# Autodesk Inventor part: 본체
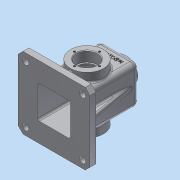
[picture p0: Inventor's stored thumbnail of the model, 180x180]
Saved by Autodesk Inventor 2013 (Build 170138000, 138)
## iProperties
Created: 2018-10
Part Number: 본체
Material: 알루미늄 6061
Document SubType Name: Modeling
Designer: Administrator
Density: 2.71 g/cm^3
Mass: 796.912 g
Surface Area: 900.061 cm^2
Volume: 294.063 cm^3
Author: Administrator
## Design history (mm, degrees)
sketch "스케치1"
  geometry: L1 (-55, 32.5)-(55, 32.5); L2 (55, 32.5)-(55, -32.5); L3 (55, -32.5)-(-55, -32.5); L4 (-55, -32.5)-(-55, 32.5); L5 (-55, 32.5)-(55, -32.5); L6 (55, 32.5)-(-55, -32.5); 1 further point
  constraints: 12 end point, 2 midpoint, 2 parallel, 1 horizontal, 1 perpendicular
  dimensions: "d0" = 110 distance of L2.end L3.end; "d1" = 65 distance of L1.end L2.end
extrude "돌출1" new body sketch "스케치1" stored distance "d2" = 65; taper "d3" = 0 deg
fillet "모깎기1" dims "d4" = 8
fillet "모깎기2" dims "d5" = 8
feature "쉘1" dims "d6" = 5
sketch "스케치2"
  geometry: L1 (57, -8)-(57, -57) reference; L2 (0, 0)-(49, 0) reference; L3 (-8, -57)-(-8, -8) reference; L4 (49, -65)-(0, -65) reference; L5 (-35.5, -92.5)-(84.5, -92.5); L6 (84.5, -92.5)-(84.5, 27.5); L7 (84.5, 27.5)-(-35.5, 27.5); L8 (-35.5, 27.5)-(-35.5, -92.5); L9 (-35.5, -92.5)-(84.5, 27.5); L10 (84.5, -92.5)-(-35.5, 27.5); A1 r 8 centre (49, -57) between (49, -65) and (57, -57) reference; A2 r 8 centre (49, -8) between (57, -8) and (49, 0) reference; A3 r 8 centre (0, -8) between (0, 0) and (-8, -8) reference; A4 r 8 centre (0, -57) between (-8, -57) and (0, -65) reference; 1 further point
  constraints: 12 end point, 2 midpoint, 2 parallel, 1 horizontal, 1 perpendicular
  dimensions: "d7" = 120 distance of L7.end L6.end; "d8" = 120 distance of L6.end L5.end
extrude "돌출2" join sketch "스케치2" distance "d9" = 10; taper "d10" = 0 deg
chamfer "모따기1" distance "d11" = 8; stored, may be unused: second distance "d12" = 2, angle "d13" = 45 deg
sketch "스케치3"
  geometry: L1 (48, -45)-(35.218, 27.493); L2 (-24.5, 55)-(24.5, 55) reference; L3 (32.5, 47)-(32.5, -45) reference; L4 (32.5, -45)-(60, -45) reference; L5 (60, -45)-(60, -55) reference; L6 (60, -55)-(27.5, -55) reference; L7 (27.5, -55)-(27.5, 47) reference; L8 (24.5, 50)-(-24.5, 50) reference; L9 (-27.5, 47)-(-27.5, -55) reference; L10 (-27.5, -55)-(-60, -55) reference; L11 (-60, -55)-(-60, -45) reference; L12 (-60, -45)-(-32.5, -45) reference; L13 (-32.5, -45)-(-32.5, 47) reference; A1 r 8 centre (-24.5, 47) between (-24.5, 55) and (-32.5, 47) reference; A2 r 8 centre (24.5, 47) between (32.5, 47) and (24.5, 55) reference; A3 r 3 centre (24.5, 47) between (27.5, 47) and (24.5, 50) reference; A4 r 3 centre (-24.5, 47) between (-24.5, 50) and (-27.5, 47) reference; 1 further point
  constraints: 2 end point, 1 point on line
  dimensions: "d14" = 12 distance from line of L5 L1.start; "d15" = 10 deg angle of L5 L1
feature "리브1" sketch "스케치3" dims "d16" = 1, "d17" = 10, "d18" = 0, "d19" = 0, "d20" = 1, "d21" = 1
fillet "모깎기3" dims "d22" = 3
fillet "모깎기4" dims "d23" = 3
node "작업 평면1"
sketch "스케치4"
  geometry: C1 r 27.5 at (24.5, -47); 1 further point
  constraints: 1 centre point, 1 coincident
  dimensions: "d26" = 55 diameter of C1
extrude "돌출3" join sketch "스케치4" stored distance "d27" = 10; taper "d28" = 0 deg
hole "구멍1" diameter "d31" = 30; stored, may be unused: countersink angle "d35" = 90 deg, drill point angle "d37" = 118 deg; dims "d29" = 10, "d30" = 10, "d32" = 6, "d33" = 35, "d34" = 17, "d36" = 20
fillet "모깎기6" dims "d38" = 0.3
chamfer "모따기2" distance "d39" = 1; stored, may be unused: second distance "d40" = 2, angle "d41" = 45 deg
sketch "스케치5"
  geometry: L1 (0, 0)-(0, 21); C1 r 18.5 at (0, 0) reference
  constraints: 2 end point, 1 vertical
  dimensions: "d42" = 21 distance of L1.start L1.end
hole "구멍2" sketch "스케치5" at (0, 21) diameter "d43" = 3.459; stored, may be unused: countersink angle "d47" = 90 deg, drill point angle "d49" = 118 deg; dims "d44" = 8, "d45" = 35, "d46" = 17, "d48" = 10
sketch "스케치6"
  geometry: L1 (-55, 27.5)-(-55, 60) reference; L2 (-55, 60)-(-45, 60) reference; L3 (-45, 60)-(-45, 32.5) reference; L4 (-45, 32.5)-(-27.5, 32.5) reference; L5 (-27.5, 32.5)-(-27.5, 47.5) reference; L6 (-27.5, 47.5)-(-22.73, 47.5) reference; L7 (-22.73, 47.5)-(-22.73, 37.5) reference; L8 (-22.73, 37.5)-(-21, 36.461) reference; L9 (-21, 36.461)-(-19.271, 37.5) reference; L10 (-19.271, 37.5)-(-19.271, 47.5) reference; L11 (-19.271, 47.5)-(-18.5, 47.5) reference; L12 (-18.5, 47.5)-(-17.5, 46.5) reference; L13 (-17.5, 46.5)-(-17.5, 30.8) reference; L14 (-17.2, 30.5)-(-15, 30.5) reference; L15 (-15, 30.5)-(-15, 27.5) reference; L16 (-15, 27.5)-(-55, 27.5) reference; L17 (50, -24.5)-(50, 24.5) reference; L18 (47, 27.5)-(15, 27.5) reference; L19 (15, 27.5)-(15, 30.5) reference; L20 (15, 30.5)-(17.2, 30.5) reference; L21 (17.5, 30.8)-(17.5, 46.5) reference; L22 (17.5, 46.5)-(18.5, 47.5) reference; L23 (18.5, 47.5)-(19.271, 47.5) reference; L24 (19.271, 47.5)-(19.271, 37.5) reference; L25 (19.271, 37.5)-(21, 36.461) reference; L26 (21, 36.461)-(22.73, 37.5) reference; L27 (22.73, 37.5)-(22.73, 47.5) reference; L28 (22.73, 47.5)-(27.5, 47.5) reference; L29 (27.5, 47.5)-(27.5, 32.5) reference; L30 (27.5, 32.5)-(47, 32.5) reference; L31 (55, 24.5)-(55, -24.5) reference; L32 (47, -32.5)-(-45, -32.5) reference; L33 (-45, -32.5)-(-45, -60) reference; L34 (-45, -60)-(-55, -60) reference; L35 (-55, -60)-(-55, -27.5) reference; L36 (-55, -27.5)-(47, -27.5) reference; L37 (-45, 42.5)-(-31.143, 42.5); A1 r 0.3 centre (-17.2, 30.8) between (-17.5, 30.8) and (-17.2, 30.5) reference; A2 r 3 centre (47, 24.5) between (50, 24.5) and (47, 27.5) reference; A3 r 0.3 centre (17.2, 30.8) between (17.2, 30.5) and (17.5, 30.8) reference; A4 r 8 centre (47, 24.5) between (55, 24.5) and (47, 32.5) reference; A5 r 8 centre (47, -24.5) between (47, -32.5) and (55, -24.5) reference; A6 r 3 centre (47, -24.5) between (47, -27.5) and (50, -24.5) reference; 1 further point
  constraints: 2 end point, 1 parallel, 1 point on line
  dimensions: "d53" = 15 distance between parallel lines of L16 L37
feature "리브2" sketch "스케치6" dims "d54" = 1, "d55" = 6, "d56" = 0, "d57" = 0, "d58" = 1, "d59" = 1
fillet "모깎기7" dims "d60" = 3
fillet "모깎기9" dims "d62" = 3
fillet "모깎기10" dims "d63" = 3
fillet "모깎기11" dims "d64" = 1
fillet "모깎기12" dims "d65" = 3
node "작업 평면2"
sketch "스케치7"
  geometry: C1 r 20 at (0, 0); 1 further point
  constraints: 1 centre point, 1 coincident
  dimensions: "d67" = 40 diameter of C1
extrude "돌출4" join sketch "스케치7" stored distance "d68" = 10; taper "d69" = 7 deg
fillet "모깎기13" dims "d70" = 3
hole "구멍3" diameter "d73" = 22.835; stored, may be unused: countersink angle "d77" = 90 deg, drill point angle "d79" = 0 deg; dims "d71" = 10, "d72" = 10, "d74" = 20, "d75" = 35, "d76" = 17, "d78" = 10
chamfer "모따기3" distance "d80" = 1; stored, may be unused: second distance "d81" = 2, angle "d82" = 45 deg
sketch "스케치8"
  geometry: 2 further points
  dimensions: "d83" = 47.5 horizontal distance of point (4.5, -12.5) point (52, -60); "d84" = 47.5 horizontal distance of point (4.5, -12.5) point (52, -60)
hole "구멍4" sketch "스케치8" at (4.5, -12.5) diameter "d85" = 10; stored, may be unused: countersink angle "d89" = 90 deg, drill point angle "d91" = 0 deg; dims "d86" = 20, "d87" = 35, "d88" = 17, "d90" = 10
sketch "스케치9"
  geometry: L1 (-8, 0)-(-8, -91) reference; L2 (4.5, 18)-(44.5, 18) reference; 1 further point
  constraints: 1 other
  dimensions: "d98" = 32.5 distance from line of point (24.5, -8) L1; "d99" = 26 distance from line of L2 point (24.5, -8)
feature "엠보싱1" sketch "스케치9" dims "d100" = 0.5, "d101" = 0
node "솔리드1"
mirror "대칭1"
pattern_circular "원형 패턴1" dims angle "d51" = 360 deg
mirror "대칭2"
pattern_linear "직사각형 패턴1" dims "d94" = 95, "d97" = 95
node "절단 모서리 투영1"
node "절단 모서리 투영2"
other parameters: "d25" = 15, "d66" = 65
